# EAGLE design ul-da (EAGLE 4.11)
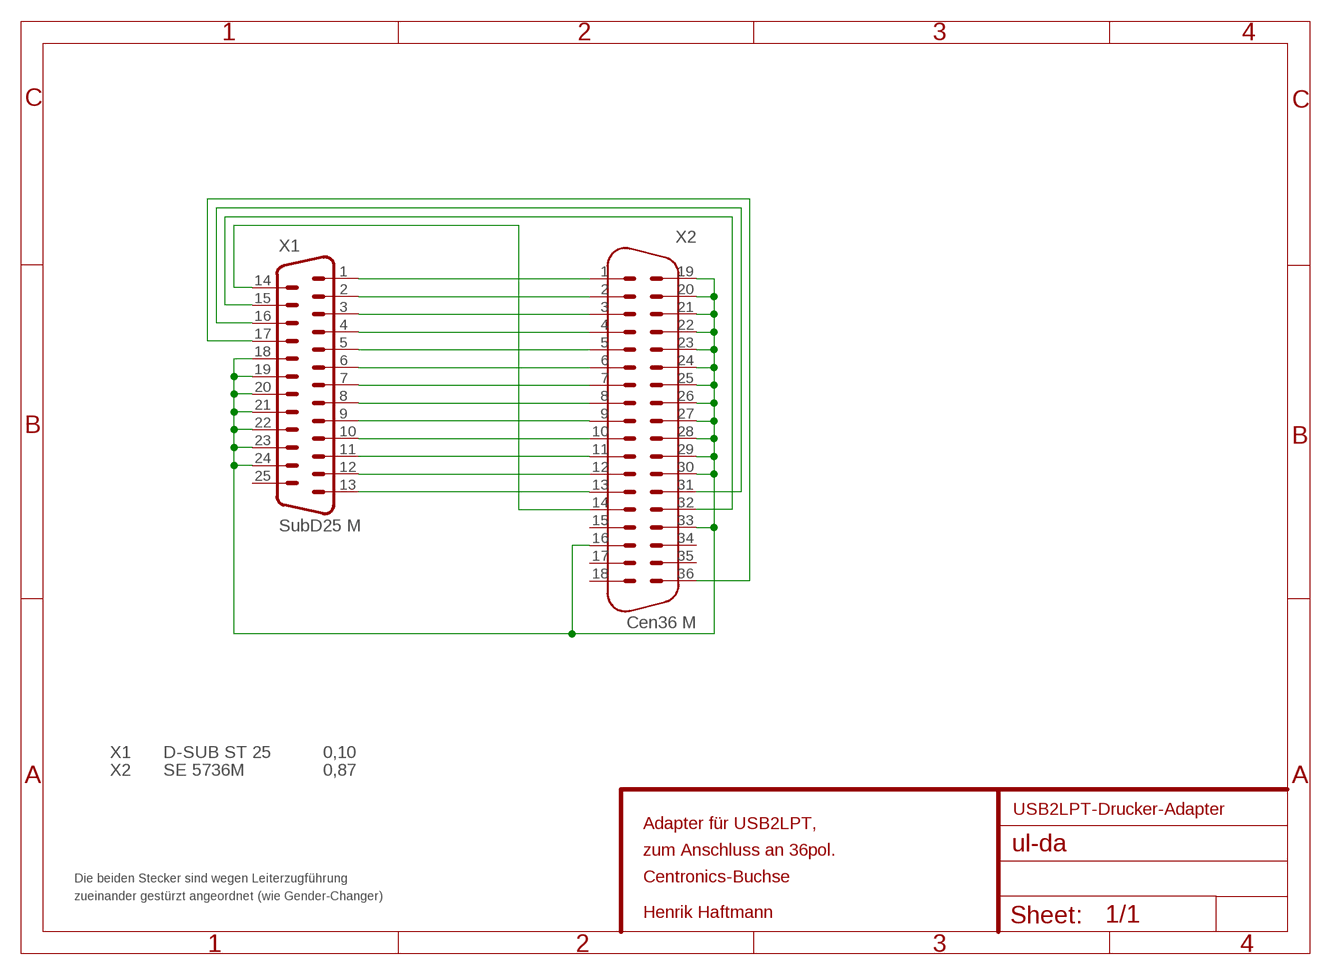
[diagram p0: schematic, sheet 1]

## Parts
X1  SubD25 M  M25K  [M25K]
X2  Cen36 M  M36K  [M36K]

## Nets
N$1: X1.1 X2.1
N$2: X1.2 X2.2
N$3: X1.3 X2.3
N$4: X1.4 X2.4
N$5: X1.5 X2.5
N$6: X1.6 X2.6
N$7: X1.7 X2.7
N$8: X1.8 X2.8
N$9: X1.9 X2.9
N$10: X1.10 X2.10
N$11: X1.11 X2.11
N$12: X1.12 X2.12
N$13: X1.13 X2.13
N$14: X1.14 X2.14
N$15: X1.15 X2.32
N$16: X1.16 X2.31
N$17: X1.17 X2.36
N$18: X1.18 X1.19 X1.20 X1.21 X1.22 X1.23 X1.24 X2.16 X2.19 X2.20 X2.21 X2.22 X2.23 X2.24 X2.25 X2.26 X2.27 X2.28 X2.29 X2.30 X2.33
Unconnected: X1.25 X2.15 X2.17 X2.18 X2.34 X2.35

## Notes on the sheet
- X1 | D-SUB ST 25 | 0,10
- X2 | SE 5736M | 0,87
- USB2LPT-Drucker-Adapter
- Adapter für USB2LPT,
- zum Anschluss an 36pol.
- Die beiden Stecker sind wegen Leiterzugführung | Centronics-Buchse
- zueinander gestürzt angeordnet (wie Gender-Changer)
- Henrik Haftmann

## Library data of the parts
X1 = ul-da:M25: SubD-Buchse korrigiert und verschönert Kantenmontage ReicheltD-SUB ST 250,14&euro;
X2 = ul-da:M36: Centronics-Stecker

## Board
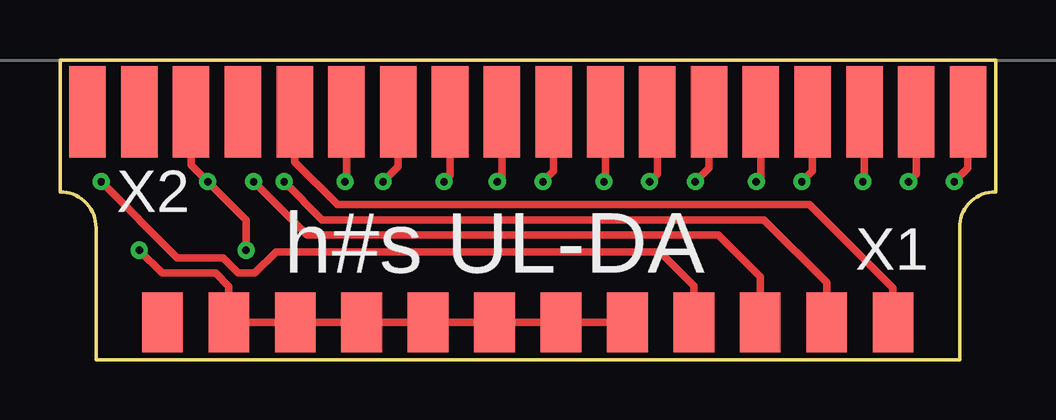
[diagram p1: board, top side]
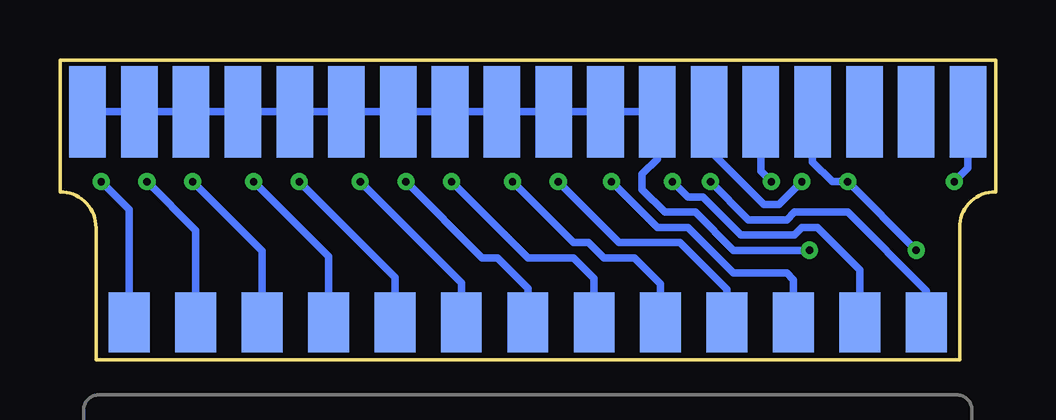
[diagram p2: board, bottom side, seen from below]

Size 39 x 12.5 mm. Coordinates in mm from the lower left corner, seen from the top.
Outline: 0,12.5 39,12.5 39,7 arc90 37.5,5.5 37.5,0 1.5,0 1.5,5.5 arc90 0,7 0,12.5
Copper layers (1*16): Top 0.035mm / dielectric 1.5mm / Bottom 0.035mm
Design rules "default": minimum track width 0.15mm, minimum drill 0.3mm, track to track 0.15mm, track to pad 0.15mm, pad to pad 0.15mm, via to via 0.15mm, smd to smd 0mil, copper to edge 0.15mm, drill to drill 0.3mm, minimum pad ring 10mil, minimum via ring 8mil, stop-mask expansion 4mil, vias tented up to drill 0mil, thermal gap 10mil

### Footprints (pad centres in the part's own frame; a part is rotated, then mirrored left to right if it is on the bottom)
M25K = smd 1.7 x 2.5: 1 16.612,-1.75; 2 13.843,-1.75; 3 11.074,-1.75; 4 8.306,-1.75; 5 5.537,-1.75; 6 2.769,-1.75; 7 0,-1.75; 8 -2.769,-1.75; 9 -5.537,-1.75; 10 -8.306,-1.75; 11 -11.074,-1.75; 12 -13.843,-1.75; 13 -16.612,-1.75 | smd 1.7 x 2.5 bottom: 14 15.227,-1.75; 15 12.459,-1.75; 16 9.69,-1.75; 17 6.921,-1.75; 18 4.153,-1.75; 19 1.384,-1.75; 20 -1.384,-1.75; 21 -4.153,-1.75; 22 -6.921,-1.75; 23 -9.69,-1.75; 24 -12.459,-1.75; 25 -15.227,-1.75
M36K = smd 1.524 x 3.81: 1 18.352,-2.159; 2 16.192,-2.159; 3 14.034,-2.159; 4 11.874,-2.159; 5 9.716,-2.159; 6 7.556,-2.159; 7 5.397,-2.159; 8 3.239,-2.159; 9 1.079,-2.159; 10 -1.079,-2.159; 11 -3.239,-2.159; 12 -5.397,-2.159; 13 -7.556,-2.159; 14 -9.716,-2.159; 15 -11.874,-2.159; 16 -14.034,-2.159; 17 -16.192,-2.159; 18 -18.352,-2.159 | smd 1.524 x 3.81 bottom: 19 18.352,-2.159; 20 16.192,-2.159; 21 14.034,-2.159; 22 11.874,-2.159; 23 9.716,-2.159; 24 7.556,-2.159; 25 5.397,-2.159; 26 3.239,-2.159; 27 1.079,-2.159; 28 -1.079,-2.159; 29 -3.239,-2.159; 30 -5.397,-2.159; 31 -7.556,-2.159; 32 -9.716,-2.159; 33 -11.874,-2.159; 34 -14.034,-2.159; 35 -16.192,-2.159; 36 -18.352,-2.159

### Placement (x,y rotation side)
X1  19.5,-0.2 180 bottom
X2  19.5,12.5 0 top

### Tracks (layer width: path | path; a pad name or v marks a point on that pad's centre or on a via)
N$1  (via drill 0.3)
  Top 0.305: X2.1 37.85,7.99 v37.28,7.42
  Bottom 0.305: X1.1 36.11,6.25 v37.28,7.42
N$2  (via drill 0.3)
  Top 0.305: X2.2 35.69,7.74 v35.38,7.42
  Bottom 0.305: X1.2 33.34,5.39 v35.38,7.42
N$3  (via drill 0.3)
  Top 0.305: X2.3 33.53,7.48 v33.47,7.42
  Bottom 0.305: X1.3 30.57,4.52 v33.47,7.42
N$4  (via drill 0.3)
  Top 0.305: X2.4 31.37,7.86 v30.93,7.42
  Bottom 0.305: X1.4 27.81,4.3 v30.93,7.42
N$5  (via drill 0.3)
  Top 0.305: X2.5 29.22,7.61 v29.02,7.42
  Bottom 0.305: X1.5 25.04,3.43 v29.02,7.42
N$6  (via drill 0.3)
  Top 0.305: X2.6 27.06,7.99 v26.48,7.42
  Bottom 0.305: X1.6 22.27,3.2 v26.48,7.42
N$7  (via drill 0.3)
  Top 0.305: X2.7 24.9,7.74 v24.58,7.42
  Bottom 0.305: v24.58,7.42 21.41,4.24 20.77,4.24 19.5,2.97 X1.7
N$8  (via drill 0.3)
  Top 0.305: X2.8 22.74,7.48 v22.68,7.42
  Bottom 0.305: v22.68,7.42 19.5,4.24 17.59,4.24 16.73,3.38 X1.8
N$9  (via drill 0.3)
  Top 0.305: X2.9 20.58,7.86 v20.14,7.42
  Bottom 0.305: v20.14,7.42 17.59,4.88 16.96,4.88 16.32,4.24 15.05,4.24 13.96,3.15 X1.9
N$10  (via drill 0.3)
  Top 0.305: X2.10 18.42,7.61 v18.23,7.42
  Bottom 0.305: X1.10 11.19,2.92 13.15,4.88 15.69,4.88 v18.23,7.42
N$11  (via drill 0.3)
  Top 0.305: X2.11 16.26,7.67 v16.01,7.42
  Bottom 0.305: v16.01,7.42 14.1,5.51 12.83,5.51 10.93,3.61 8.71,3.61 8.43,3.33 X1.11
N$12  (via drill 0.3)
  Top 0.305: X2.12 14.1,8.05 v13.47,7.42
  Bottom 0.305: v13.47,7.42 12.83,6.79 12.2,6.79 10.61,5.2 8.39,5.2 8.07,5.51 7.44,5.51 5.66,3.74 X1.12
N$13  (via drill 0.3)
  Top 0.305: X2.13 11.94,7.48 v11.88,7.42
  Bottom 0.305: X1.13 2.89,2.87 6.16,6.15 8.39,6.15 8.71,5.83 10.29,5.83 v11.88,7.42
N$14
  Top 0.305: X2.14 9.78,8.25 11.56,6.47 31.25,6.47 34.73,2.99 X1.14
N$15  (via drill 0.3)
  Top 0.305: v9.34,7.42 10.93,5.83 29.34,5.83 31.96,3.22 X1.15
  Bottom 0.305: X2.32 9.78,7.86 v9.34,7.42
N$16  (via drill 0.3)
  Top 0.305: v8.07,7.42 10.29,5.2 27.44,5.2 29.19,3.45 X1.16
  Bottom 0.305: X2.31 11.94,8.75 9.66,6.47 9.02,6.47 v8.07,7.42
N$17  (via drill 0.3)
  Top 0.305: v1.72,7.42 4.89,4.24 6.8,4.24 7.44,3.61 8.11,3.61 9,4.5 25,4.5 26.42,3.08 X1.17
  Bottom 0.305: X2.36 1.15,7.99 v1.72,7.42
N$18  (via drill 0.3)
  Top 0.305: X2.16 5.47,8.12 v6.16,7.42 7.75,5.83 v7.75,4.56 | 20.77,1.55 X1.19 | 20.77,1.55 X1.18 | 20.77,1.55 X1.20 15.69,1.55 | 15.69,1.55 X1.21 X1.22 9.97,1.55 | 15.69,1.55 15.69,1.71 | 9.97,1.55 X1.23 | 9.97,1.55 X1.24 7.04,3.05 6.48,3.61 4.26,3.61 v3.31,4.56
  Bottom 0.305: 35.38,10.34 X2.20 | 35.38,10.34 X2.19 | 35.38,10.34 X2.21 31.56,10.34 | 31.56,10.34 X2.22 | 31.56,10.34 X2.23 27.12,10.34 | 27.12,10.34 X2.24 | 27.12,10.34 X2.25 22.68,10.34 | 22.68,10.34 X2.26 | 22.68,10.34 X2.27 X2.28 X2.29 X2.30 | X2.30 13.79,10.34 13.79,10.6 | X2.33 7.63,8.25 6.8,7.42 v6.16,7.42 v3.31,4.56 | X2.30 14.1,8.37 14.74,7.74 14.74,7.1 13.79,6.15 12.52,6.15 10.93,4.56 v7.75,4.56

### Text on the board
tNames: h#s UL-DA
